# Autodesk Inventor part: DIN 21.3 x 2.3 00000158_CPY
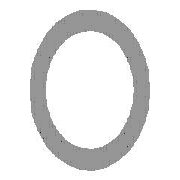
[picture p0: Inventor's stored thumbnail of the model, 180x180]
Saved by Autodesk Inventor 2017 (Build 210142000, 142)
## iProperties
Created: 2016-02
Part Number: DIN 21.3 x 2.3 00000158_CPY
Material: Steel, Mild
Description: Pipe
Document SubType Name: Modeling
Standard: DIN
Designer: iusti
Standard Revision: 2006-07
Standards Organization: DIN
Language: en-US
Size Designation: 21.3 x 2.3
Categories: <MemberInstance><Categories><Category DisplayName="Structural Shapes" InternalName="089c4875-fa83-4c05-b084-43b9cc11f5ed" Mnemonic="GRDR"><CategoryParameter Dis
Stock Number: 21.3 x 2.3
Density: 7.85 g/cm^3
Appearance: Semi-Polished
_CCFamilyMember: 1
_CCFamilyDisplayName: DIN EN 10210-2 - Pipe
_FrameMemberDoc: Frame Member File
_Version: 15.0.0
_GetPNFromCC: 1
IsCustomPart: 1
Author: iusti
G_L: 510.650 mm
G_W: 21.300 mm
G_H: 21.300 mm
+AA30E1D5-0686-4E1F-BB21-01C88EDD7D39+CUTDETAIL1: Miter 45.00 deg
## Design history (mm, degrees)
node "Start plane"
node "End plane"
sketch "Sketch"
  geometry: C1 r 8.35 at (0, 0); C2 r 10.65 at (0, 0); 2 further points
  constraints: 3 coincident, 2 centre point
  dimensions: "d0" = 21.3 diameter of C2 (= G_H); "d1" = 2.3 radial gap between concentric circles of C2 C1 (= G_T)
extrude "Body" new body sketch "Sketch" stored distance "d2" = 510.65 (= G_L); taper "d3" = 0 deg
node "Driven Length"
  sketch "Sketch3"
    geometry: L1 (0, 0)-(10, 0) reference
    constraints: 2 end point, 1 horizontal
  workplane "Work Plane3"
  sketch "Sketch4"
    geometry: L1 (-2, 0)-(12, 0) reference; L2 (-2, 510.65)-(12, 510.65) reference
    dimensions: "d7" = 510.65 distance between parallel lines of L1 L2 (derived)
workplane "Work Plane4"
split "Split1"
body "Solid1"
other parameters: "G_H" = 21.3 [user parameter; used in 1 equation term], "G_T" = 2.3 [user parameter; used in 1 equation term], "G_L" = 510.65 (= d7) [user parameter; used in 1 equation term], "G_OFFSET_START" = 0 [user parameter; used in 1 equation term], "G_OFFSET_END" = 10.65 [user parameter; used in 1 equation term], "d4" = 0 (computed from G_OFFSET_START), "d5" = 510.65 (= G_OFFSET_END + B_L), "d6" = 90 deg
